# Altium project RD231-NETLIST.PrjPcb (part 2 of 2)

## Sheet 3.SchDoc
size 420 x 297 mm
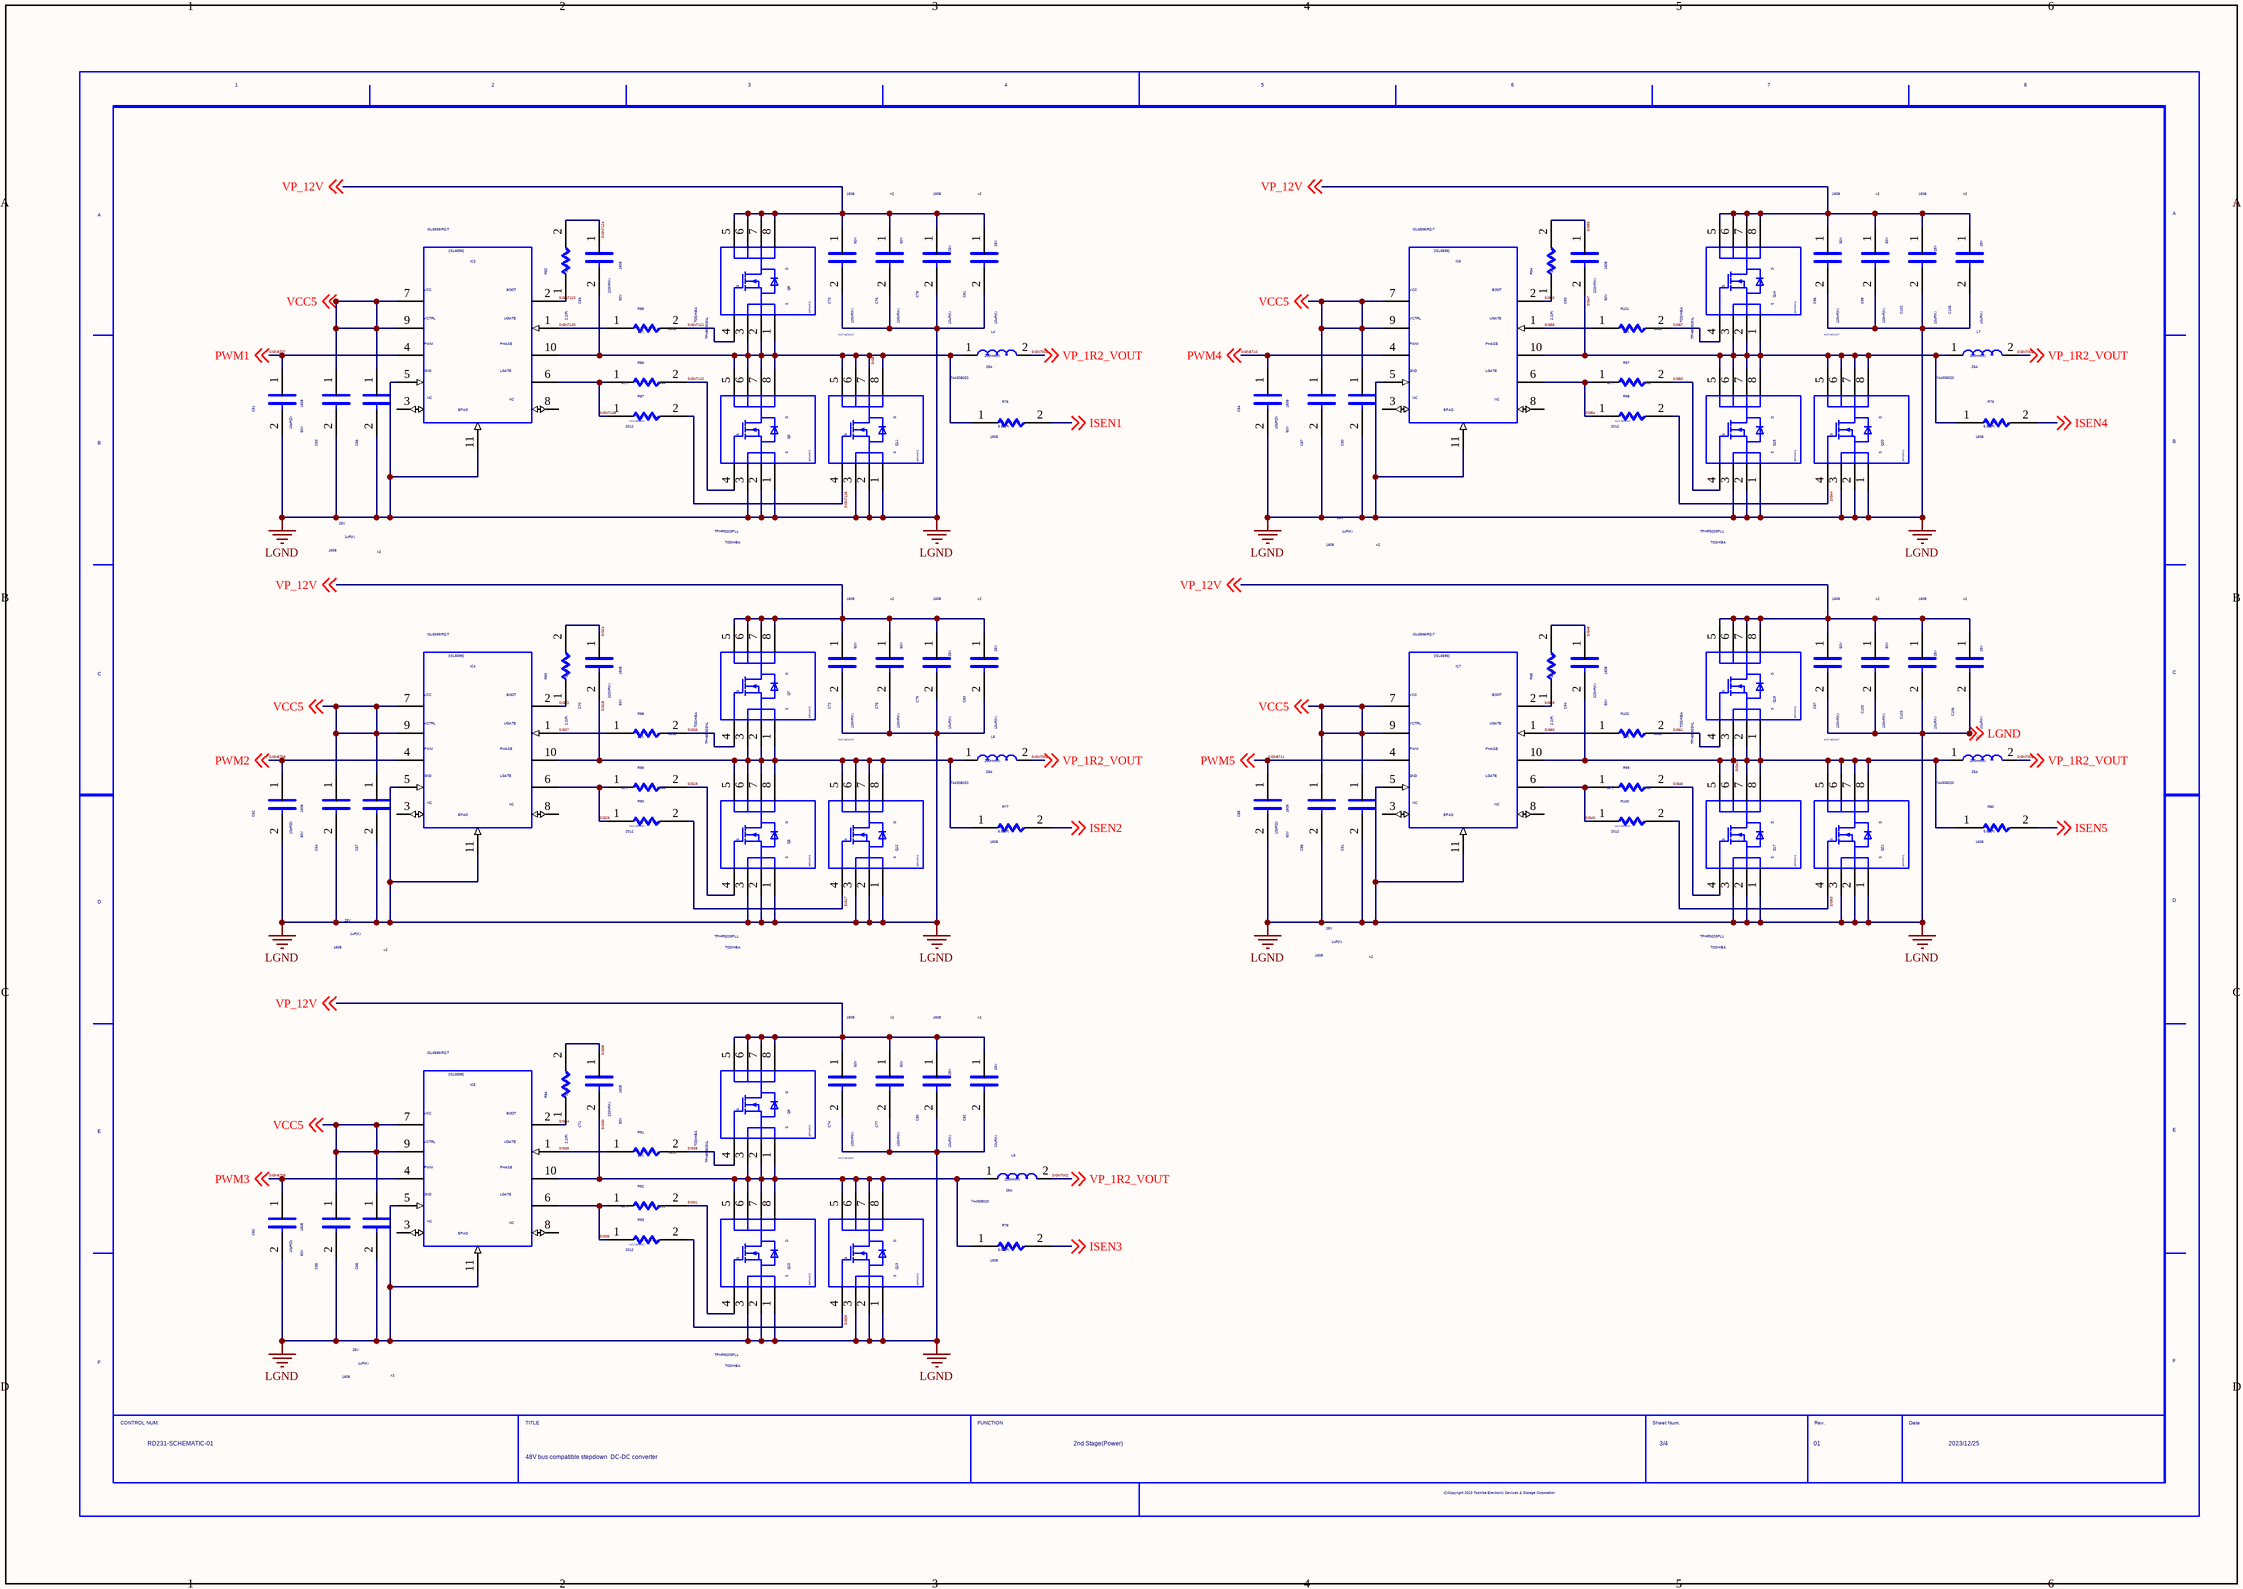
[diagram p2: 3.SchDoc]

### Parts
(Parts that share a designator on the sheet are numbered #1, #2 ... from top to bottom, then left to right.)
C60  VAL1: 10pF(D)  VAL2: 50V  SIZECODESMD: 1608  (hidden comment: C)
C61  VAL1: 10pF(D)  VAL2: 50V  SIZECODESMD: 1608  (hidden comment: C)
C62  VAL1: 10pF(D)  VAL2: 50V  SIZECODESMD: 1608  (hidden comment: C)
C63  C  (value not drawn)
C64  C  (value not drawn)
C65  C  (value not drawn)
C66  VAL1: 1uF(K)  VAL2: 25V  SIZECODESMD: 1608  (hidden comment: C)
C67  VAL1: 1uF(K)  VAL2: 25V  SIZECODESMD: 1608  (hidden comment: C)
C68  VAL1: 1uF(K)  VAL2: 25V  SIZECODESMD: 1608  (hidden comment: C)
C69  VAL1: 220nF(K)  VAL2: 50V  SIZECODESMD: 1608  (hidden comment: C)
C70  VAL1: 220nF(K)  VAL2: 50V  SIZECODESMD: 1608  (hidden comment: C)
C71  VAL1: 220nF(K)  VAL2: 50V  SIZECODESMD: 1608  (hidden comment: C)
C72  VAL1: 100nF(K)  VAL2: 50V  SIZECODESMD: 1608  (hidden comment: C)
C73  VAL1: 100nF(K)  VAL2: 50V  SIZECODESMD: 1608  (hidden comment: C)
C74  VAL1: 100nF(K)  VAL2: 50V  SIZECODESMD: 1608  (hidden comment: C)
C75  VAL1: 100nF(K)  VAL2: 50V  (hidden comment: C)
C76  VAL1: 100nF(K)  VAL2: 50V  (hidden comment: C)
C77  VAL1: 100nF(K)  VAL2: 50V  (hidden comment: C)
C78  VAL1: 10uF(K)  VAL2: 25V  SIZECODESMD: 1608  (hidden comment: C)
C79  VAL1: 10uF(K)  VAL2: 25V  SIZECODESMD: 1608  (hidden comment: C)
C80  VAL1: 10uF(K)  VAL2: 25V  SIZECODESMD: 1608  (hidden comment: C)
C81  VAL1: 10uF(K)  VAL2: 25V  (hidden comment: C)
C82  VAL1: 10uF(K)  VAL2: 25V  (hidden comment: C)
C83  VAL1: 10uF(K)  VAL2: 25V  (hidden comment: C)
C84  VAL1: 10pF(D)  VAL2: 50V  SIZECODESMD: 1608  (hidden comment: C)
C85  VAL1: 10pF(D)  VAL2: 50V  SIZECODESMD: 1608  (hidden comment: C)
C87  C  (value not drawn)
C88  C  (value not drawn)
C90  VAL1: 1uF(K)  VAL2: 25V  SIZECODESMD: 1608  (hidden comment: C)
C91  VAL1: 1uF(K)  VAL2: 25V  SIZECODESMD: 1608  (hidden comment: C)
C93  VAL1: 220nF(K)  VAL2: 50V  SIZECODESMD: 1608  (hidden comment: C)
C94  VAL1: 220nF(K)  VAL2: 50V  SIZECODESMD: 1608  (hidden comment: C)
C96  VAL1: 100nF(K)  VAL2: 50V  SIZECODESMD: 1608  (hidden comment: C)
C97  VAL1: 100nF(K)  VAL2: 50V  SIZECODESMD: 1608  (hidden comment: C)
C99  VAL1: 100nF(K)  VAL2: 50V  (hidden comment: C)
C100  VAL1: 100nF(K)  VAL2: 50V  (hidden comment: C)
C102  VAL1: 10uF(K)  VAL2: 25V  SIZECODESMD: 1608  (hidden comment: C)
C103  VAL1: 10uF(K)  VAL2: 25V  SIZECODESMD: 1608  (hidden comment: C)
C105  VAL1: 10uF(K)  VAL2: 25V  (hidden comment: C)
C106  VAL1: 10uF(K)  VAL2: 25V  (hidden comment: C)
IC3  VAL3: ISL6596IRZ-T  (hidden comment: ISL6596)
IC4  VAL3: ISL6596IRZ-T  (hidden comment: ISL6596)
IC5  VAL3: ISL6596IRZ-T  (hidden comment: ISL6596)
IC6  VAL3: ISL6596IRZ-T  (hidden comment: ISL6596)
IC7  VAL3: ISL6596IRZ-T  (hidden comment: ISL6596)
L4  VAL1: 200nH(M)  VAL2: 25A  VAL3: 744308020  (hidden comment: L)
L5  VAL1: 200nH(M)  VAL2: 25A  VAL3: 744308020  (hidden comment: L)
L6  VAL1: 200nH(M)  VAL2: 25A  VAL3: 744308020  (hidden comment: L)
L7  VAL1: 200nH(M)  VAL2: 25A  VAL3: 744308020  (hidden comment: L)
L8  VAL1: 200nH(M)  VAL2: 25A  VAL3: 744308020  (hidden comment: L)
Q5  VAL3: TPH8R903NL  USERCOMPTEXT3: TOSHIBA  (hidden comment: MFNKR2)
Q6  VAL3: TPHR9203PL1  USERCOMPTEXT3: TOSHIBA  (hidden comment: MFNKR2)
Q7  VAL3: TPH8R903NL  USERCOMPTEXT3: TOSHIBA  (hidden comment: MFNKR2)
Q8  VAL3: TPHR9203PL1  USERCOMPTEXT3: TOSHIBA  (hidden comment: MFNKR2)
Q9  VAL3: TPH8R903NL  USERCOMPTEXT3: TOSHIBA  (hidden comment: MFNKR2)
Q10  VAL3: TPHR9203PL1  USERCOMPTEXT3: TOSHIBA  (hidden comment: MFNKR2)
Q11  NOTMOUNT: NOT MOUNT  (hidden comment: MFNKR2)
Q12  NOTMOUNT: NOT MOUNT  (hidden comment: MFNKR2)
Q13  NOTMOUNT: NOT MOUNT  (hidden comment: MFNKR2)
Q14  VAL3: TPH8R903NL  USERCOMPTEXT3: TOSHIBA  (hidden comment: MFNKR2)
Q15  VAL3: TPHR9203PL1  USERCOMPTEXT3: TOSHIBA  (hidden comment: MFNKR2)
Q16  VAL3: TPH8R903NL  USERCOMPTEXT3: TOSHIBA  (hidden comment: MFNKR2)
Q17  VAL3: TPHR9203PL1  USERCOMPTEXT3: TOSHIBA  (hidden comment: MFNKR2)
Q20  NOTMOUNT: NOT MOUNT  (hidden comment: MFNKR2)
Q21  NOTMOUNT: NOT MOUNT  (hidden comment: MFNKR2)
R76  VAL1: 5.6k(F)  SIZECODESMD: 1608  (hidden comment: R)
R77  VAL1: 5.6k(F)  SIZECODESMD: 1608  (hidden comment: R)
R78  VAL1: 5.6k(F)  SIZECODESMD: 1608  (hidden comment: R)
R79  VAL1: 5.6k(F)  SIZECODESMD: 1608  (hidden comment: R)
R80  VAL1: 5.6k(F)  SIZECODESMD: 1608  (hidden comment: R)
R82  VAL1: 2.2(F)  SIZECODESMD: 2012  (hidden comment: R)
R83  VAL1: 2.2(F)  SIZECODESMD: 2012  (hidden comment: R)
R84  VAL1: 2.2(F)  SIZECODESMD: 2012  (hidden comment: R)
R85  VAL1: 1(F)  SIZECODESMD: 2012  (hidden comment: R)
R86  VAL1: 1(F)  SIZECODESMD: 2012  (hidden comment: R)
R87  NOTMOUNT: NOT MOUNT  SIZECODESMD: 2012  (hidden comment: R)
R88  VAL1: 1(F)  SIZECODESMD: 2012  (hidden comment: R)
R89  VAL1: 1(F)  SIZECODESMD: 2012  (hidden comment: R)
R90  NOTMOUNT: NOT MOUNT  SIZECODESMD: 2012  (hidden comment: R)
R91  VAL1: 1(F)  SIZECODESMD: 2012  (hidden comment: R)
R92  VAL1: 1(F)  SIZECODESMD: 2012  (hidden comment: R)
R93  NOTMOUNT: NOT MOUNT  SIZECODESMD: 2012  (hidden comment: R)
R94  VAL1: 2.2(F)  SIZECODESMD: 2012  (hidden comment: R)
R95  VAL1: 2.2(F)  SIZECODESMD: 2012  (hidden comment: R)
R97  VAL1: 1(F)  SIZECODESMD: 2012  (hidden comment: R)
R98  NOTMOUNT: NOT MOUNT  SIZECODESMD: 2012  (hidden comment: R)
R99  VAL1: 1(F)  SIZECODESMD: 2012  (hidden comment: R)
R100  NOTMOUNT: NOT MOUNT  SIZECODESMD: 2012  (hidden comment: R)
R101  VAL1: 1(F)  SIZECODESMD: 2012  (hidden comment: R)
R102  VAL1: 1(F)  SIZECODESMD: 2012  (hidden comment: R)
U?#3  DATE: 2023/12/25  FUNCTION: 2nd Stage(Power)  DRAWINGNUMBER: RD231-SCHEMATIC-01  SHEETNUMBER: 3/4  REVISION: 01  TITLE: 48V bus compatible stepdown / DC-DC converter  (hidden comment: WAKU_DEF100)

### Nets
LGND: C60.2 C61.2 C62.2 C63.2 C64.2 C65.2 C66.2 C67.2 C68.2 C72.2 C73.2 C74.2 C75.2 C76.2 C77.2 C78.2 C79.2 C80.2 C81.2 C82.2 C83.2 C84.2 C85.2 C87.2 C88.2 C90.2 C91.2 C96.2 C97.2 C99.2 C100.2 C102.2 C103.2 C105.2 C106.2 IC3.5 IC3.11 IC4.5 IC4.11 IC5.5 IC5.11 IC6.5 IC6.11 IC7.5 IC7.11 Q6.1 Q6.2 Q6.3 Q8.1 Q8.2 Q8.3 Q10.1 Q10.2 Q10.3 Q11.1 Q11.2 Q11.3 Q12.1 Q12.2 Q12.3 Q13.1 Q13.2 Q13.3 Q15.1 Q15.2 Q15.3 Q17.1 Q17.2 Q17.3 Q20.1 Q20.2 Q20.3 Q21.1 Q21.2 Q21.3 ; off-sheet LGND
ISEN1: R76.2 ; off-sheet ISEN1
ISEN2: R77.2 ; off-sheet ISEN2
ISEN3: R78.2 ; off-sheet ISEN3
ISEN4: R79.2 ; off-sheet ISEN4
ISEN5: R80.2 ; off-sheet ISEN5
SIG5: C69.2 IC3.10 L4.1 Q5.1 Q5.2 Q5.3 Q6.5 Q6.6 Q6.7 Q6.8 Q11.5 Q11.6 Q11.7 Q11.8 R76.1
SIG17: Q12.4 R90.2
SIG18: C70.2 IC4.10 L5.1 Q7.1 Q7.2 Q7.3 Q8.5 Q8.6 Q8.7 Q8.8 Q12.5 Q12.6 Q12.7 Q12.8 R77.1
SIG19: Q8.4 R89.2
SIG22: IC4.2 R83.1
SIG23: IC4.6 R89.1 R90.1
SIG24: C70.1 R83.2
SIG26: Q7.4 R88.2
SIG27: IC4.1 R88.1
SIG29: Q13.4 R93.2
SIG30: C71.2 IC5.10 L6.1 Q9.1 Q9.2 Q9.3 Q10.5 Q10.6 Q10.7 Q10.8 Q13.5 Q13.6 Q13.7 Q13.8 R78.1
SIG31: Q10.4 R92.2
SIG34: IC5.2 R84.1
SIG35: IC5.6 R92.1 R93.1
SIG36: C71.1 R84.2
SIG38: Q9.4 R91.2
SIG39: IC5.1 R91.1
SIG41: C94.2 IC7.10 L8.1 Q16.1 Q16.2 Q16.3 Q17.5 Q17.6 Q17.7 Q17.8 Q21.5 Q21.6 Q21.7 Q21.8 R80.1
SIG43: IC7.6 R99.1 R100.1
SIG44: Q20.4 R98.2
SIG46: Q17.4 R99.2
SIG47: C93.2 IC6.10 L7.1 Q14.1 Q14.2 Q14.3 Q15.5 Q15.6 Q15.7 Q15.8 Q20.5 Q20.6 Q20.7 Q20.8 R79.1
SIG48: C94.1 R95.2
SIG49: IC7.2 R95.1
SIG50: Q15.4 R97.2
SIG53: IC6.2 R94.1
SIG54: IC6.6 R97.1 R98.1
SIG55: C93.1 R94.2
SIG57: Q14.4 R101.2
SIG58: IC6.1 R101.1
SIG60: IC7.1 R102.1
SIG61: Q16.4 R102.2
SIG63: Q21.4 R100.2
SIGN6707: C61.1 IC3.4 ; off-sheet PWM1  [also labelled PWM1]
SIGN6708: C62.1 IC4.4 ; off-sheet PWM2  [also labelled PWM2]
SIGN6709: C60.1 IC5.4 ; off-sheet PWM3  [also labelled PWM3]
SIGN6710: C84.1 IC6.4 ; off-sheet PWM4  [also labelled PWM4]
SIGN6711: C85.1 IC7.4 ; off-sheet PWM5  [also labelled PWM5]
SIGN7002: L4.2 L5.2 L6.2 L7.2 L8.2 ; off-sheet VP_1R2_VOUT  [also labelled VP_1R2_VOUT]
SIGN7120: IC3.1 R85.1
SIGN7121: Q5.4 R85.2
SIGN7122: Q6.4 R86.2
SIGN7123: IC3.2 R82.1
SIGN7124: C69.1 R82.2
SIGN7125: Q11.4 R87.2
SIGN7126: IC3.6 R86.1 R87.1
VCC5: C63.1 C64.1 C65.1 C66.1 C67.1 C68.1 C87.1 C88.1 C90.1 C91.1 IC3.7 IC3.9 IC4.7 IC4.9 IC5.7 IC5.9 IC6.7 IC6.9 IC7.7 IC7.9 ; off-sheet VCC5
VP_12V: C72.1 C73.1 C74.1 C75.1 C76.1 C77.1 C78.1 C79.1 C80.1 C81.1 C82.1 C83.1 C96.1 C97.1 C99.1 C100.1 C102.1 C103.1 C105.1 C106.1 Q5.5 Q5.6 Q5.7 Q5.8 Q7.5 Q7.6 Q7.7 Q7.8 Q9.5 Q9.6 Q9.7 Q9.8 Q14.5 Q14.6 Q14.7 Q14.8 Q16.5 Q16.6 Q16.7 Q16.8 ; off-sheet VP_12V

Not connected (* = marked no-connect by the designer): IC3 3 8; IC4 3 8; IC5 3 8; IC6 3 8; IC7 3 8

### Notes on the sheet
- x2

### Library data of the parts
C60-C62 C84 C85 = C: FNPARTSNAMEG: CHIP CERAMIC CAPACITOR (1608); OriginalSymbolOrigin: (2540,7620); FNCLASSCODEG: P03-03; PCODE: P03039185229; USEWITHSCHEMA: YES; MFMOUNTSYMBOLP: 80; FUNCN: G36030011013; MFFORMINGDIVP: KC; MFPACKAGEMETHOP: S; MFSOLDERINGPROP: .; COMPONENTNAME: G36030011013_package; GCOUNT: 1; TOLERANCE: D
C63-C65 C87 C88 = C: FNPARTSNAMEG: CHIP CERAMIC CAPACITOR (1608); OriginalSymbolOrigin: (2540,7620); FNCLASSCODEG: P03-03; PCODE: P03039992230; USEWITHSCHEMA: YES; VAL1: 1uF(K); VAL2: 25V; MFMOUNTSYMBOLP: 80; FUNCN: G36030011433; SIZECODESMD: 1608; MFFORMINGDIVP: KC; MFPACKAGEMETHOP: S; MFSOLDERINGPROP: .; COMPONENTNAME: G36030011433_package; GCOUNT: 1
C66-C68 C78-C80 C90 C91 C102 C103 = C: FNPARTSNAMEG: CHIP CERAMIC CAPACITOR (1608); OriginalSymbolOrigin: (2540,7620); FNCLASSCODEG: P03-03; PCODE: P03039992230; USEWITHSCHEMA: YES; MFMOUNTSYMBOLP: 80; FUNCN: G36030011433; MFFORMINGDIVP: KC; MFPACKAGEMETHOP: S; MFSOLDERINGPROP: .; COMPONENTNAME: G36030011433_package; GCOUNT: 1
C69-C71 C93 C94 = C: FNPARTSNAMEG: CHIP CERAMIC CAPACITOR (1608); OriginalSymbolOrigin: (2540,7620); FNCLASSCODEG: P03-03; PCODE: P03039ABE123; USEWITHSCHEMA: YES; MFMOUNTSYMBOLP: 80; FUNCN: G36030104104; MFFORMINGDIVP: KC; MFPACKAGEMETHOP: S; MFSOLDERINGPROP: .; COMPONENTNAME: G36030104104_package; GCOUNT: 1
C72-C74 C96 C97 = C: FNPARTSNAMEG: CHIP CERAMIC CAPACITOR (1608); OriginalSymbolOrigin: (2540,7620); FNCLASSCODEG: P03-03; PCODE: P03039996139; USEWITHSCHEMA: YES; MFMOUNTSYMBOLP: 80; FUNCN: G36030011419; MFFORMINGDIVP: KC; MFPACKAGEMETHOP: S; MFSOLDERINGPROP: .; COMPONENTNAME: G36030011419_package; GCOUNT: 1
C75-C77 C99 C100 = C: FNPARTSNAMEG: CHIP CERAMIC CAPACITOR (1608); OriginalSymbolOrigin: (2540,7620); FNCLASSCODEG: P03-03; PCODE: P03039996139; USEWITHSCHEMA: YES; MFMOUNTSYMBOLP: 80; FUNCN: G36030011419; SIZECODESMD: 1608; MFFORMINGDIVP: KC; MFPACKAGEMETHOP: S; MFSOLDERINGPROP: .; COMPONENTNAME: G36030011419_package; GCOUNT: 1
C81-C83 C105 C106 = C: FNPARTSNAMEG: CHIP CERAMIC CAPACITOR (1608); OriginalSymbolOrigin: (2540,7620); FNCLASSCODEG: P03-03; PCODE: P03039992230; USEWITHSCHEMA: YES; MFMOUNTSYMBOLP: 80; FUNCN: G36030011433; SIZECODESMD: 1608; MFFORMINGDIVP: KC; MFPACKAGEMETHOP: S; MFSOLDERINGPROP: .; COMPONENTNAME: G36030011433_package; GCOUNT: 1
IC3-IC7 = ISL6596: PARTS: 1; SAVECOUNT: 32; SAVEAREA0: -56845,-25936,87219,39707; TIME: 14:04:55; UPDATEUSER: sptcae13; UPDATETIME: 17:09:04; DEVICENAME: 74HC244AF; DEVICE: 74VHC245; PKG_TYPE: 20PIN; LEVEL: STD; HETERO: 74VHC245,74VHC245_P; OriginalSymbolOrigin: (5080,27940); COMP: G36470287016
L4-L8 = L: OriginalSymbolOrigin: (2540,5080); USEWITHSCHEMA: YES; OUMEMAKERKATAMEI: 7443082022; OUMEMAKER: Wurth; COMPONENTNAME: pinass:L_func:L; GCOUNT: 1
Q5-Q10 Q14-Q17 = MFNKR2: SAVEAREA0: -9199,-39,32138,22820; TIME: 18:57:44; UPDATEUSER: q91866sr; UPDATETIME: 12:36:02; SAVECOUNT: 10; OriginalSymbolOrigin: (5080,20320); USEWITHSCHEMA: YES; OUMEMAKERKATAMEI: TPH6R003NL; COMPONENTNAME: MFNKR2_MFNKR2; GCOUNT: 1
Q11-Q13 Q20 Q21 = MFNKR2: SAVEAREA0: -9199,-39,32138,22820; TIME: 18:57:44; UPDATEUSER: q91866sr; UPDATETIME: 12:36:02; SAVECOUNT: 10; OriginalSymbolOrigin: (5080,20320); USEWITHSCHEMA: YES; OUMEMAKERKATAMEI: TPH6R003NL; OUMEMAKER: TOSHIBA; COMPONENTNAME: MFNKR2_MFNKR2; GCOUNT: 1
R76-R80 = R: OriginalSymbolOrigin: (5080,5080); VAL2: 62.5mW
R82-R84 R94 R95 = R: FNPARTSNAMEG: CHIP RESISTOR (2012); OriginalSymbolOrigin: (5080,5080); FNCLASSCODEG: P01-08; PCODE: P01048019214; USEWITHSCHEMA: YES; VAL2: 125mW; NUMBEROFELEMENT: 0; MFMOUNTSYMBOLP: 90; FUNCN: G36010106012; MFFORMINGDIVP: KC; MFPACKAGEMETHOP: S; MFSOLDERINGPROP: .; COMPONENTNAME: G36010106012_package; GCOUNT: 1
R85 R86 R88 R89 R91 R92 R97 R99 R101 R102 = R: FNPARTSNAMEG: CHIP RESISTOR (2012); OriginalSymbolOrigin: (5080,5080); FNCLASSCODEG: P01-08; PCODE: P01048017210; USEWITHSCHEMA: YES; VAL2: 125mW; NUMBEROFELEMENT: 0; MFMOUNTSYMBOLP: 90; FUNCN: G36010106081; MFFORMINGDIVP: KC; MFPACKAGEMETHOP: S; MFSOLDERINGPROP: .; COMPONENTNAME: G36010106081_package; GCOUNT: 1
R87 R90 R93 R98 R100 = R: FNPARTSNAMEG: CHIP RESISTOR (2012); OriginalSymbolOrigin: (5080,5080); FNCLASSCODEG: P01-08; PCODE: P01048017210; USEWITHSCHEMA: YES; NUMBEROFELEMENT: 0; MFMOUNTSYMBOLP: 90; FUNCN: G36010106081; MFFORMINGDIVP: KC; MFPACKAGEMETHOP: S; MFSOLDERINGPROP: .; COMPONENTNAME: G36010106081_package; GCOUNT: 1
U?#3 = WAKU_DEF100: PLOTTIME: HH:MM; SAVEAREA0: 315434,-7824,400773,39368; TIME: 14:26:19; UPDATEUSER: sptcae13; UPDATETIME: 11:36:35; SAVECOUNT: 8; OriginalSymbolOrigin: (10160,284480)

## Sheet 4.SchDoc
size 420 x 297 mm
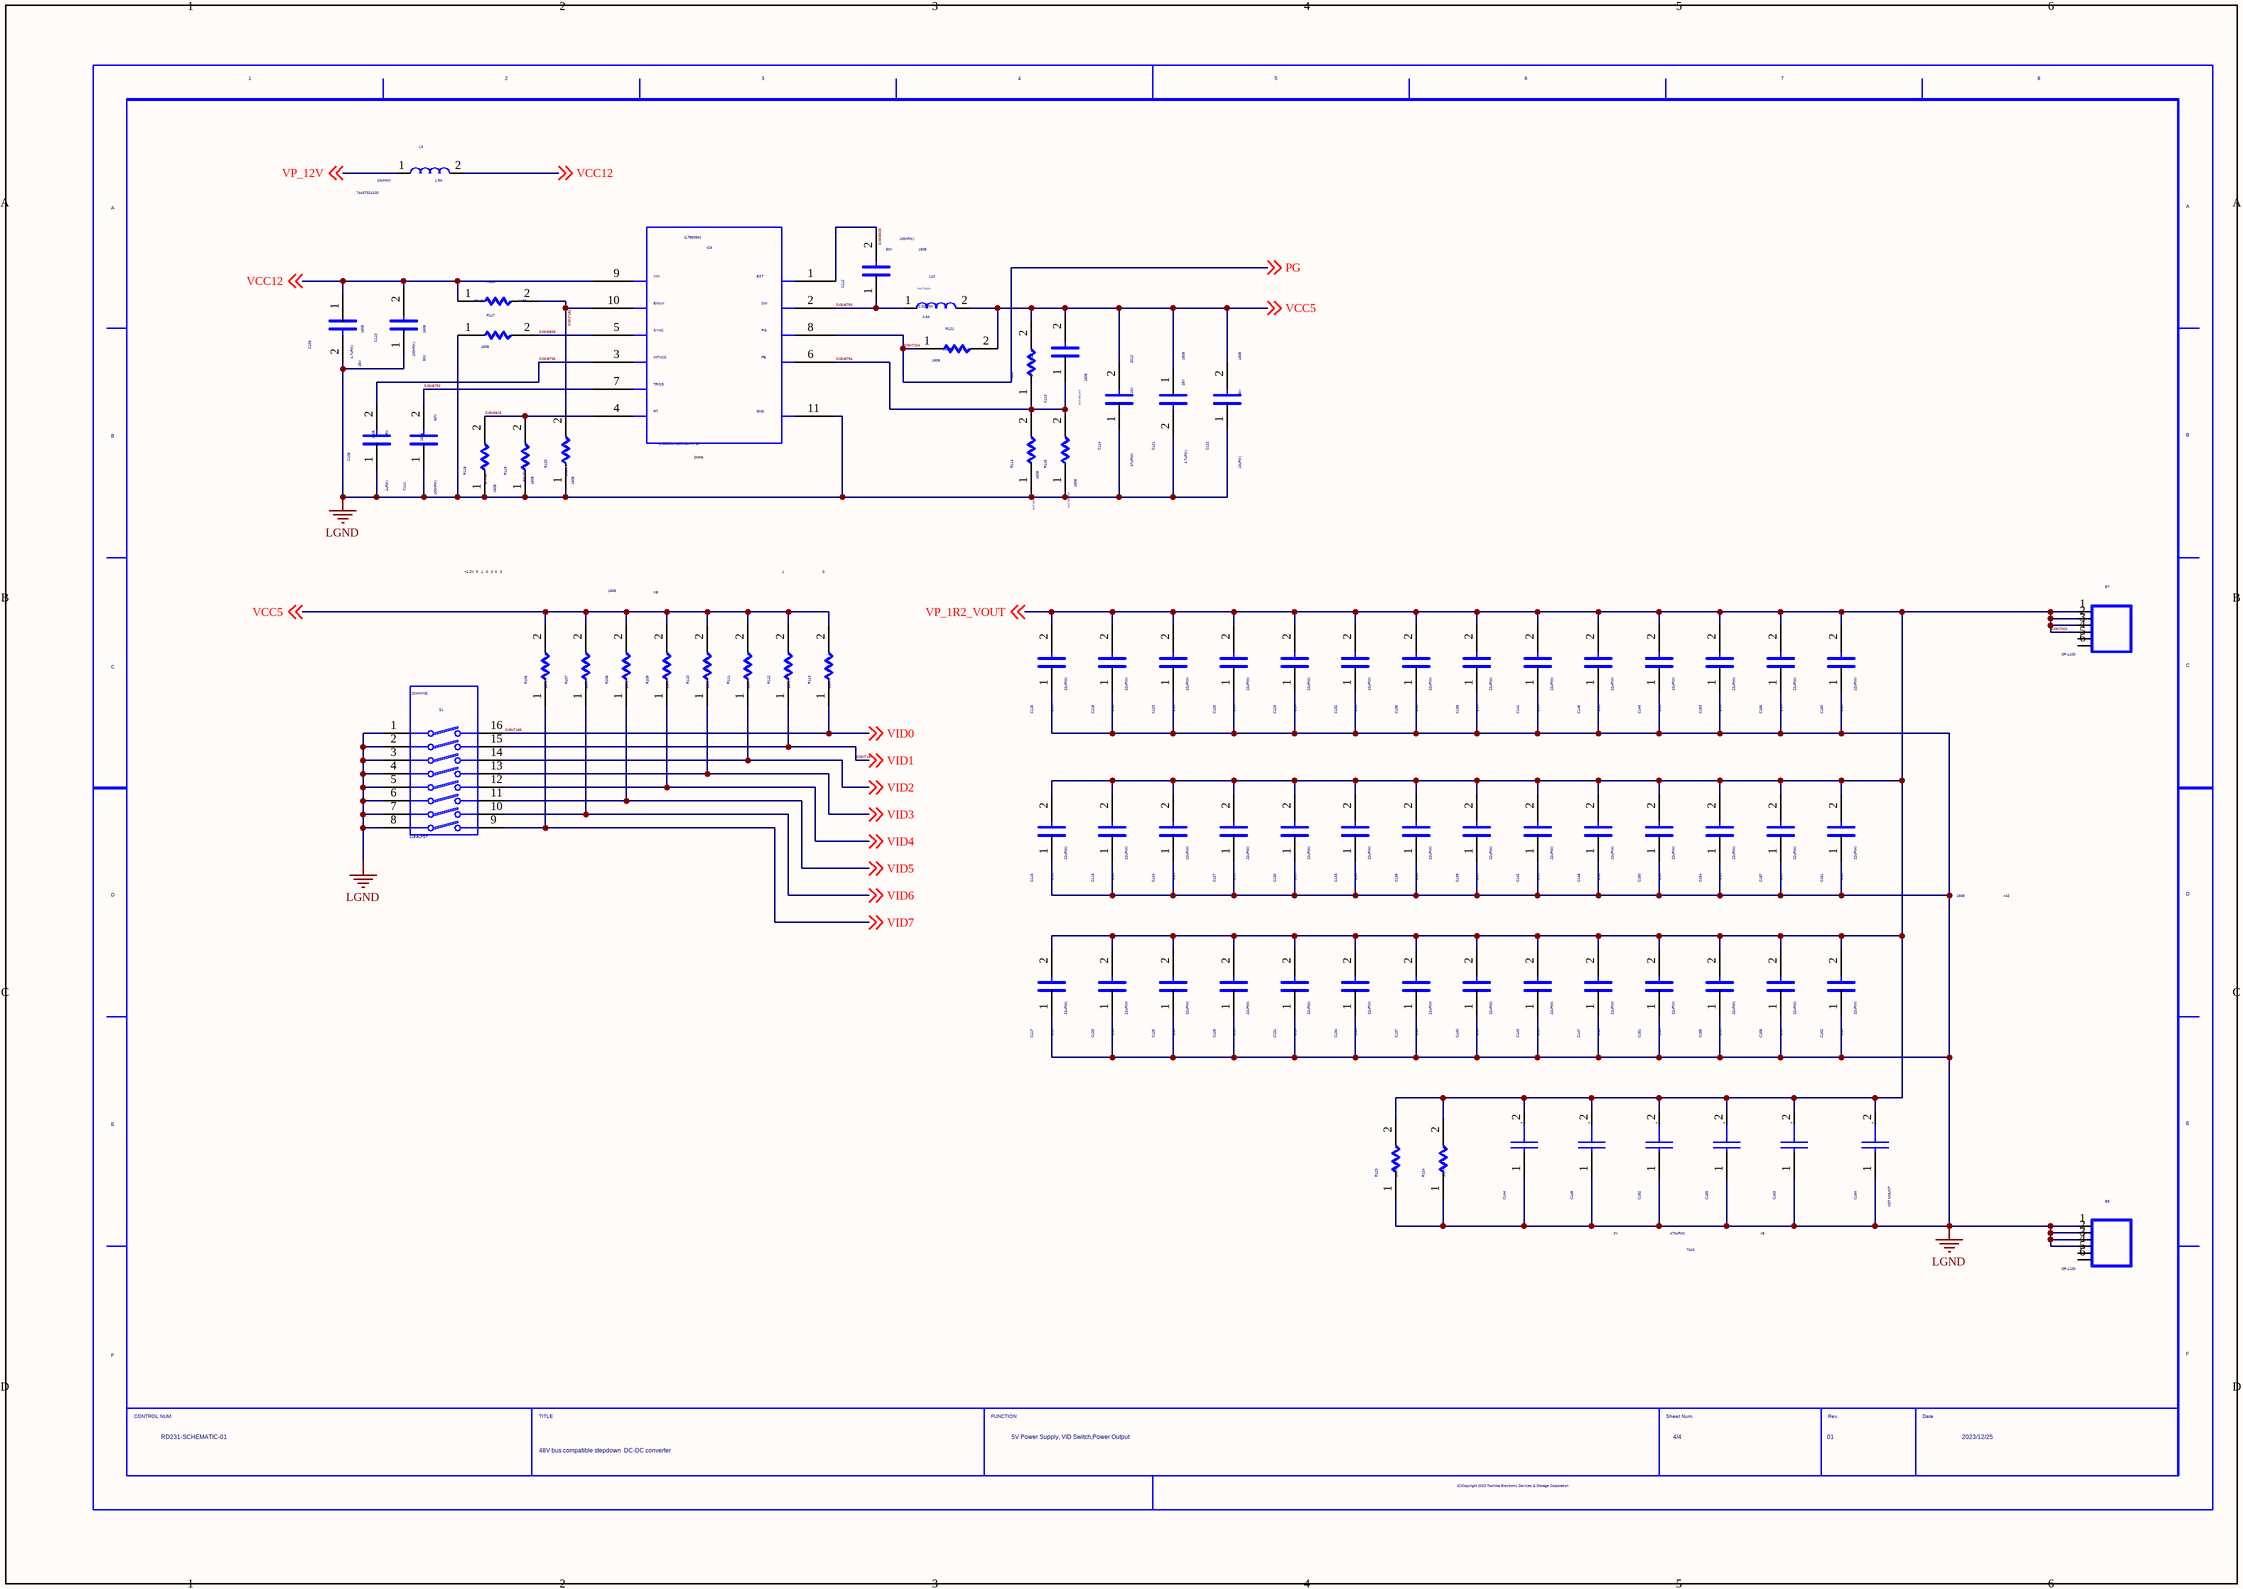
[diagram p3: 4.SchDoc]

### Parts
(Parts that share a designator on the sheet are numbered #1, #2 ... from top to bottom, then left to right.)
C108  VAL1: 1uF(K)  VAL2: 25V  SIZECODESMD: 1608  (hidden comment: C)
C109  VAL1: 4.7uF(K)  VAL2: 25V  SIZECODESMD: 1608  (hidden comment: C)
C110  VAL1: 100nF(K)  VAL2: 50V  SIZECODESMD: 1608  (hidden comment: C)
C111  VAL1: 100nF(K)  VAL2: 50V  SIZECODESMD: 1608  (hidden comment: C)
C112  VAL1: 100nF(K)  VAL2: 50V  SIZECODESMD: 1608  (hidden comment: C)
C113  NOTMOUNT: NOT MOUNT  SIZECODESMD: 1608  (hidden comment: C)
C114  VAL1: 47uF(M)  VAL2: 10V  SIZECODESMD: 2012  (hidden comment: C)
C115  VAL1: 22uF(M)  VAL2: 6.3V  (hidden comment: C)
C116  VAL1: 22uF(M)  VAL2: 6.3V  (hidden comment: C)
C117  VAL1: 22uF(M)  VAL2: 6.3V  (hidden comment: C)
C118  VAL1: 22uF(M)  VAL2: 6.3V  (hidden comment: C)
C119  VAL1: 22uF(M)  VAL2: 6.3V  (hidden comment: C)
C120  VAL1: 22uF(M)  VAL2: 6.3V  (hidden comment: C)
C121  VAL1: 4.7uF(K)  VAL2: 25V  SIZECODESMD: 1608  (hidden comment: C)
C122  VAL1: 10uF(K)  VAL2: 25V  SIZECODESMD: 1608  (hidden comment: C)
C123  VAL1: 22uF(M)  VAL2: 6.3V  (hidden comment: C)
C124  VAL1: 22uF(M)  VAL2: 6.3V  (hidden comment: C)
C125  VAL1: 22uF(M)  VAL2: 6.3V  (hidden comment: C)
C126  VAL1: 22uF(M)  VAL2: 6.3V  (hidden comment: C)
C127  VAL1: 22uF(M)  VAL2: 6.3V  (hidden comment: C)
C128  VAL1: 22uF(M)  VAL2: 6.3V  (hidden comment: C)
C129  VAL1: 22uF(M)  VAL2: 6.3V  (hidden comment: C)
C130  VAL1: 22uF(M)  VAL2: 6.3V  (hidden comment: C)
C131  VAL1: 22uF(M)  VAL2: 6.3V  (hidden comment: C)
C132  VAL1: 22uF(M)  VAL2: 6.3V  (hidden comment: C)
C133  VAL1: 22uF(M)  VAL2: 6.3V  (hidden comment: C)
C134  VAL1: 22uF(M)  VAL2: 6.3V  (hidden comment: C)
C135  VAL1: 22uF(M)  VAL2: 6.3V  (hidden comment: C)
C136  VAL1: 22uF(M)  VAL2: 6.3V  (hidden comment: C)
C137  VAL1: 22uF(M)  VAL2: 6.3V  (hidden comment: C)
C138  VAL1: 22uF(M)  VAL2: 6.3V  (hidden comment: C)
C139  VAL1: 22uF(M)  VAL2: 6.3V  (hidden comment: C)
C140  VAL1: 22uF(M)  VAL2: 6.3V  (hidden comment: C)
C141  VAL1: 22uF(M)  VAL2: 6.3V  (hidden comment: C)
C142  VAL1: 22uF(M)  VAL2: 6.3V  (hidden comment: C)
C143  VAL1: 22uF(M)  VAL2: 6.3V  (hidden comment: C)
C144  VAL1: 470uF(M)  VAL2: 2V  SIZECODESMD: 7343  (hidden comment: CP)
C145  VAL1: 22uF(M)  VAL2: 6.3V  (hidden comment: C)
C146  VAL1: 22uF(M)  VAL2: 6.3V  (hidden comment: C)
C147  VAL1: 22uF(M)  VAL2: 6.3V  (hidden comment: C)
C148  CP  (value not drawn)
C149  VAL1: 22uF(M)  VAL2: 6.3V  (hidden comment: C)
C150  VAL1: 22uF(M)  VAL2: 6.3V  (hidden comment: C)
C151  VAL1: 22uF(M)  VAL2: 6.3V  (hidden comment: C)
C152  CP  (value not drawn)
C153  VAL1: 22uF(M)  VAL2: 6.3V  (hidden comment: C)
C154  VAL1: 22uF(M)  VAL2: 6.3V  (hidden comment: C)
C155  VAL1: 22uF(M)  VAL2: 6.3V  (hidden comment: C)
C156  VAL1: 22uF(M)  VAL2: 6.3V  (hidden comment: C)
C157  VAL1: 22uF(M)  VAL2: 6.3V  (hidden comment: C)
C158  VAL1: 22uF(M)  VAL2: 6.3V  (hidden comment: C)
C159  CP  (value not drawn)
C160  VAL1: 22uF(M)  VAL2: 6.3V  (hidden comment: C)
C161  VAL1: 22uF(M)  VAL2: 6.3V  SIZECODESMD: 1608  (hidden comment: C)
C162  VAL1: 22uF(M)  VAL2: 6.3V  (hidden comment: C)
C163  CP  (value not drawn)
C164  NOTMOUNT: NOT MOUNT  (hidden comment: CP)
E7  VAL3: OP-1100  (hidden comment: EB1)
E8  VAL3: OP-1100  (hidden comment: EB1)
IC9  COMP: LT8609AHDDM-5#TRPBF  (hidden comment: LT8609A)
L3  VAL1: 10uH(M)  VAL2: 1.5A  VAL3: 74437324100  (hidden comment: L)
L10  COMP: 744774022  VAL1: 2.2uH(M)  VAL2: 4.6A  (hidden comment: L)
R106  VAL1: 10k(F)  SIZECODESMD: 1608  (hidden comment: R)
R107  VAL1: 10k(F)  (hidden comment: R)
R108  VAL1: 10k(F)  (hidden comment: R)
R109  VAL1: 10k(F)  (hidden comment: R)
R110  VAL1: 10k(F)  (hidden comment: R)
R111  VAL1: 10k(F)  (hidden comment: R)
R112  VAL1: 10k(F)  (hidden comment: R)
R113  VAL1: 10k(F)  (hidden comment: R)
R114  NOTMOUNT: NOT MOUNT  SIZECODESMD: 1608  (hidden comment: R)
R115  NOTMOUNT: NOT MOUNT  SIZECODESMD: 1608  (hidden comment: R)
R116  VAL1: 33k(F)  SIZECODESMD: 1608  (hidden comment: R)
R117  VAL1: 0  SIZECODESMD: 1608  (hidden comment: R)
R118  VAL1: 27k(D)  SIZECODESMD: 1608  (hidden comment: R)
R119  VAL1: 56k(D)  SIZECODESMD: 1608  (hidden comment: R)
R120  VAL1: 3.9k(F)  SIZECODESMD: 1608  (hidden comment: R)
R121  VAL1: 10k(F)  SIZECODESMD: 1608  (hidden comment: R)
R122  VAL1: 0  SIZECODESMD: 1608  (hidden comment: R)
R123  VAL1: 1k(F)  (hidden comment: R)
R124  VAL1: 1k(F)  (hidden comment: R)
S1  COMP: 219-8LPST  (hidden comment: SWMX8)
U?#4  DATE: 2023/12/25  FUNCTION: 5V Power Supply, VID Switch,Power Output  DRAWINGNUMBER: RD231-SCHEMATIC-01  SHEETNUMBER: 4/4  REVISION: 01  TITLE: 48V bus compatible stepdown / DC-DC converter  (hidden comment: WAKU_DEF100)

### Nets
LGND: C108.1 C109.2 C110.1 C111.1 C114.1 C115.1 C116.1 C117.1 C118.1 C119.1 C120.1 C121.2 C122.1 C123.1 C124.1 C125.1 C126.1 C127.1 C128.1 C129.1 C130.1 C131.1 C132.1 C133.1 C134.1 C135.1 C136.1 C137.1 C138.1 C139.1 C140.1 C141.1 C142.1 C143.1 C144.1 C145.1 C146.1 C147.1 C148.1 C149.1 C150.1 C151.1 C152.1 C153.1 C154.1 C155.1 C156.1 C157.1 C158.1 C159.1 C160.1 C161.1 C162.1 C163.1 C164.1 E8.1 E8.2 E8.3 E8.4 IC9.11 R114.1 R115.1 R117.1 R118.1 R119.1 R120.1 R123.1 R124.1 S1.1 S1.2 S1.3 S1.4 S1.5 S1.6 S1.7 S1.8
SIGN6792: C111.2 IC9.7
SIGN6793: C112.1 IC9.2 L10.1
SIGN6794: C113.1 IC9.6 R114.2 R115.2 R122.1
SIGN6796: C108.2 IC9.3
SIGN6815: IC9.4 R118.2 R119.2
SIGN6828: C112.2 IC9.1
SIGN6838: IC9.5 R117.2
SIGN7002: C115.2 C116.2 C117.2 C118.2 C119.2 C120.2 C123.2 C124.2 C125.2 C126.2 C127.2 C128.2 C129.2 C130.2 C131.2 C132.2 C133.2 C134.2 C135.2 C136.2 C137.2 C138.2 C139.2 C140.2 C141.2 C142.2 C143.2 C144.2 C145.2 C146.2 C147.2 C148.2 C149.2 C150.2 C151.2 C152.2 C153.2 C154.2 C155.2 C156.2 C157.2 C158.2 C159.2 C160.2 C161.2 C162.2 C163.2 C164.2 E7.1 E7.2 E7.3 E7.4 R123.2 R124.2 ; off-sheet VP_1R2_VOUT  [also labelled VP_1R2_VOUT]
SIGN7182: IC9.10 R116.2 R120.2
SIGN7186: R113.1 S1.16 ; off-sheet VID0  [also labelled VID0]
SIGN7187: R112.1 S1.15 ; off-sheet VID1  [also labelled VID1]
SIGN7204: IC9.8 R121.1 ; off-sheet PG  [also labelled PG]
VCC5: C113.2 C114.2 C121.1 C122.2 L10.2 R106.2 R107.2 R108.2 R109.2 R110.2 R111.2 R112.2 R113.2 R121.2 R122.2 ; off-sheet VCC5
VCC12: C109.1 C110.2 IC9.9 L3.2 R116.1 ; off-sheet VCC12
VID2: R111.1 S1.14 ; off-sheet VID2
VID3: R110.1 S1.13 ; off-sheet VID3
VID4: R109.1 S1.12 ; off-sheet VID4
VID5: R108.1 S1.11 ; off-sheet VID5
VID6: R107.1 S1.10 ; off-sheet VID6
VID7: R106.1 S1.9 ; off-sheet VID7
VP_12V: L3.1 ; off-sheet VP_12V

Not connected (* = marked no-connect by the designer): E7 5 6; E8 5 6

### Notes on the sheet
- (near IC9) 2MHz
- +1.2V  0   1   0   0  0   0
- X8
- 1
- 0
- x42
- x5

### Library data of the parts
C108 = C: FNPARTSNAMEG: CHIP CERAMIC CAPACITOR (1608); OriginalSymbolOrigin: (2540,7620); USEWITHSCHEMA: YES; FUNCN: G36030011433; MFPACKAGEMETHOP: S; COMPONENTNAME: G36030011433_package; GCOUNT: 1; FNCLASSCODEG: P03-03; MFMOUNTSYMBOLP: 80; MFFORMINGDIVP: KC; MFSOLDERINGPROP: .; PCODE: P03039992230
C109 = C: FNPARTSNAMEG: CHIP CERAMIC CAPACITOR (1608); OriginalSymbolOrigin: (2540,7620); FNCLASSCODEG: P03-03; PCODE: P03B000000MS; USEWITHSCHEMA: YES; MFMOUNTSYMBOLP: 80; FUNCN: GDM030000053; MFFORMINGDIVP: KC; MFPACKAGEMETHOP: S; MFSOLDERINGPROP: .; COMPONENTNAME: GDM030000053_package; GCOUNT: 1
C110 C112 = C: FNPARTSNAMEG: CHIP CERAMIC CAPACITOR (1608); OriginalSymbolOrigin: (2540,7620); USEWITHSCHEMA: YES; FUNCN: G36030104036; MFPACKAGEMETHOP: S; COMPONENTNAME: G36030104036_package; GCOUNT: 1; FNCLASSCODEG: P03-03; PCODE: P03039A6F224; MFMOUNTSYMBOLP: 80; MFFORMINGDIVP: KC; MFSOLDERINGPROP: .
C111 = C: PARTCOMMENT: 代表セル<KC0008> がフットプリントに登録されていません。; FNPARTSNAMEG: CHIP CERAMIC CAPACITOR (1608); OriginalSymbolOrigin: (2540,7620); USEWITHSCHEMA: YES; FUNCN: GDM030001137; MFPACKAGEMETHOP: S; COMPONENTNAME: GDM030001137_package; GCOUNT: 1; FNCLASSCODEG: P03-03; PCODE: P03B000001KW; MFMOUNTSYMBOLP: 80; MFFORMINGDIVP: KC; MFSOLDERINGPROP: .
C113 = C: FNPARTSNAMEG: CHIP CERAMIC CAPACITOR (1608); OriginalSymbolOrigin: (2540,7620); USEWITHSCHEMA: YES; FUNCN: G36030011013; MFPACKAGEMETHOP: S; COMPONENTNAME: G36030011013_package; GCOUNT: 1; FNCLASSCODEG: P03-03; PCODE: P03039185229; MFMOUNTSYMBOLP: 80; MFFORMINGDIVP: KC; MFSOLDERINGPROP: .; TOLERANCE: D
C114 = C: FNPARTSNAMEG: CHIP CERAMIC CAPACITOR (2012); OriginalSymbolOrigin: (2540,7620); USEWITHSCHEMA: YES; FUNCN: GDM030000019; MFPACKAGEMETHOP: S; COMPONENTNAME: GDM030000019_package; GCOUNT: 1; FNCLASSCODEG: P03-03; PCODE: P03B0000004U; MFMOUNTSYMBOLP: 80; MFFORMINGDIVP: KC; MFSOLDERINGPROP: .
C115-C120 C123-C143 C145-C147 C149-C151 C153-C158 C160 C162 = C: FNPARTSNAMEG: CHIP CERAMIC CAPACITOR (1608); OriginalSymbolOrigin: (2540,7620); USEWITHSCHEMA: YES; FUNCN: GDM030000053; MFPACKAGEMETHOP: S; COMPONENTNAME: GDM030000053_package; GCOUNT: 1; FNCLASSCODEG: P03-03; MFMOUNTSYMBOLP: 80; SIZECODESMD: 1608; MFFORMINGDIVP: KC; MFSOLDERINGPROP: .; PCODE: P03B000000MS
C121 = C: as C66 on sheet 3
C122 C161 = C: FNPARTSNAMEG: CHIP CERAMIC CAPACITOR (1608); OriginalSymbolOrigin: (2540,7620); USEWITHSCHEMA: YES; FUNCN: GDM030000053; MFPACKAGEMETHOP: S; COMPONENTNAME: GDM030000053_package; GCOUNT: 1; FNCLASSCODEG: P03-03; MFMOUNTSYMBOLP: 80; MFFORMINGDIVP: KC; MFSOLDERINGPROP: .; PCODE: P03B000000MS
C144 = CP: FNPARTSCODEG: C; FNPARTSNAMEG: POSCAP (TPB); SAVEAREA0: -1450,-153,20294,13055; SAVECOUNT: 52; TIME: 15:02:55; UPDATEUSER: fukuda-y; UPDATETIME: 16:13:42; OriginalSymbolOrigin: (2540,10160); USEWITHSCHEMA: YES; FUNCN: G36030149044; GCOUNT: 1; COMPONENTNAME: G36030149044_package; FNCLASSCODEG: P03-02; PCODE: P03217004212; MFMOUNTSYMBOLP: 80; MFFORMINGDIVP: KD; MFPACKAGEMETHOP: S; MFSOLDERINGPROP: .
C148 C152 C159 C163 = CP: FNPARTSCODEG: C; FNPARTSNAMEG: POSCAP (TPB); SAVEAREA0: -1450,-153,20294,13055; SAVECOUNT: 52; TIME: 15:02:55; UPDATEUSER: fukuda-y; UPDATETIME: 16:13:42; OriginalSymbolOrigin: (2540,10160); USEWITHSCHEMA: YES; FUNCN: G36030149044; GCOUNT: 1; COMPONENTNAME: G36030149044_package; VAL1: 470uF(M); VAL2: 2V; FNCLASSCODEG: P03-02; PCODE: P03217004212; MFMOUNTSYMBOLP: 80; SIZECODESMD: 7343; MFFORMINGDIVP: KD; MFPACKAGEMETHOP: S; MFSOLDERINGPROP: .
C164 = CP: FNPARTSCODEG: C; FNPARTSNAMEG: POSCAP (TPB); SAVEAREA0: -1450,-153,20294,13055; SAVECOUNT: 52; TIME: 15:02:55; UPDATEUSER: fukuda-y; UPDATETIME: 16:13:42; OriginalSymbolOrigin: (2540,10160); USEWITHSCHEMA: YES; FUNCN: G36030149044; GCOUNT: 1; COMPONENTNAME: G36030149044_package; FNCLASSCODEG: P03-02; PCODE: P03217004212; MFMOUNTSYMBOLP: 80; SIZECODESMD: 7343; MFFORMINGDIVP: KD; MFPACKAGEMETHOP: S; MFSOLDERINGPROP: .
E7 E8 = EB1: SAVEAREA0: -19495,-9575,29572,17273; TIME: 17:33:04; UPDATEUSER: sptcae13; UPDATETIME: 17:37:19; SAVECOUNT: 4; OriginalSymbolOrigin: (0,10160)
IC9 = LT8609A: TIME: 17:49:40; UPDATEUSER: q91866sr; UPDATETIME: 14:18:47; SAVECOUNT: 44; SAVEAREA0: -19850,-898,65678,46399; OriginalSymbolOrigin: (7620,43180); USEWITHSCHEMA: YES; GCOUNT: 1; OUMEMAKER: Analog Devices; COMPONENTNAME: pinass:LT8609A_func:LT8609A
L3 L10 = L: OriginalSymbolOrigin: (2540,5080); USEWITHSCHEMA: YES; OUMEMAKER: Wurth Elektronik; COMPONENTNAME: L.L; GCOUNT: 1
R106 = R: FNPARTSNAMEG: CHIP RESISTOR (1608); OriginalSymbolOrigin: (5080,5080); FNCLASSCODEG: P01-08; PCODE: P01042049A26; USEWITHSCHEMA: YES; VAL2: 100mW; NUMBEROFELEMENT: 0; MFMOUNTSYMBOLP: 80; COMP: G36010027034; MFFORMINGDIVP: KC; MFPACKAGEMETHOP: S; MFSOLDERINGPROP: .; TOLERANCE: F; COMPONENTNAME: G36010027034_package
R107-R113 = R: FNPARTSNAMEG: CHIP RESISTOR (1608); OriginalSymbolOrigin: (5080,5080); FNCLASSCODEG: P01-08; PCODE: P01042049A26; USEWITHSCHEMA: YES; VAL2: 100mW; NUMBEROFELEMENT: 0; MFMOUNTSYMBOLP: 80; COMP: G36010027034; MFFORMINGDIVP: KC; MFPACKAGEMETHOP: S; MFSOLDERINGPROP: .; TOLERANCE: F; COMPONENTNAME: G36010027034_package; SIZECODESMD: 1608
R114 = R: FNPARTSNAMEG: CHIP RESISTOR (1608); OriginalSymbolOrigin: (5080,5080); FNCLASSCODEG: P01-08; PCODE: P01042409226; USEWITHSCHEMA: YES; NUMBEROFELEMENT: 0; MFMOUNTSYMBOLP: 80; COMP: G36010104216; MFFORMINGDIVP: KC; MFPACKAGEMETHOP: S; MFSOLDERINGPROP: .; TOLERANCE: F; COMPONENTNAME: G36010104216_package
R115 = R: FNPARTSNAMEG: CHIP RESISTOR (1608); OriginalSymbolOrigin: (5080,5080); FNCLASSCODEG: P01-08; PCODE: P01042237423; USEWITHSCHEMA: YES; NUMBEROFELEMENT: 0; MFMOUNTSYMBOLP: 80; COMP: G36010103110; MFFORMINGDIVP: KC; MFPACKAGEMETHOP: S; MFSOLDERINGPROP: .; TOLERANCE: J; COMPONENTNAME: G36010103110_package
R116 = R: FNPARTSNAMEG: CHIP RESISTOR (1608); OriginalSymbolOrigin: (5080,5080); FNCLASSCODEG: P01-08; USEWITHSCHEMA: YES; VAL2: 100mW; COMP: G36010027171; COMPONENTNAME: G36010027171_package; GCOUNT: 1; PCODE: P01042295621; NUMBEROFELEMENT: 0; MFMOUNTSYMBOLP: 80; MFFORMINGDIVP: KC; MFPACKAGEMETHOP: S; MFSOLDERINGPROP: .; TOLERANCE: F
R117 R122 = R: PARTCOMMENT: 代表セル<KC0008> がフットプリントに登録されていません。; FNPARTSNAMEG: CHIP JUMPER 1608TYPE; OriginalSymbolOrigin: (5080,5080); FNCLASSCODEG: P01-08; USEWITHSCHEMA: YES; COMP: K0100346; COMPONENTNAME: K0100346_package; GCOUNT: 1
R118 = R: FNPARTSNAMEG: CHIP RESISTOR (1608); OriginalSymbolOrigin: (5080,5080); FNCLASSCODEG: P01-08; PCODE: P01117063117; USEWITHSCHEMA: YES; VAL2: 62.5mW; NUMBEROFELEMENT: 0; MFMOUNTSYMBOLP: 80; COMP: G36010129592; MFFORMINGDIVP: KC; MFPACKAGEMETHOP: S; MFSOLDERINGPROP: .; COMPONENTNAME: G36010129592_package; GCOUNT: 1
R119 = R: FNPARTSNAMEG: CHIP RESISTOR (1608); OriginalSymbolOrigin: (5080,5080); FNCLASSCODEG: P01-08; PCODE: P01042600623; USEWITHSCHEMA: YES; VAL2: 62.5mW; NUMBEROFELEMENT: 0; MFMOUNTSYMBOLP: 80; COMP: G36010014676; MFFORMINGDIVP: KC; MFPACKAGEMETHOP: S; MFSOLDERINGPROP: .; COMPONENTNAME: G36010014676_package; GCOUNT: 1
R120 = R: FNPARTSNAMEG: CHIP RESISTOR (1608); OriginalSymbolOrigin: (5080,5080); FNCLASSCODEG: P01-08; PCODE: P01042262227; USEWITHSCHEMA: YES; VAL2: 100mW; NUMBEROFELEMENT: 0; MFMOUNTSYMBOLP: 80; COMP: G36010104254; MFFORMINGDIVP: KC; MFPACKAGEMETHOP: S; MFSOLDERINGPROP: .; COMPONENTNAME: G36010104254_package; GCOUNT: 1; TOLERANCE: F
R121 = R: FNPARTSNAMEG: CHIP RESISTOR (1608); OriginalSymbolOrigin: (5080,5080); FNCLASSCODEG: P01-08; USEWITHSCHEMA: YES; VAL2: 100mW; COMP: G36010027034; COMPONENTNAME: G36010027034_package; GCOUNT: 1; PCODE: P01042049A26; NUMBEROFELEMENT: 0; MFMOUNTSYMBOLP: 80; MFFORMINGDIVP: KC; MFPACKAGEMETHOP: S; MFSOLDERINGPROP: .; TOLERANCE: F
R123 R124 = R: FNPARTSNAMEG: CHIP RESISTOR (1608); OriginalSymbolOrigin: (5080,5080); FNCLASSCODEG: P01-08; PCODE: P01042521225; USEWITHSCHEMA: YES; VAL2: 100mW; NUMBEROFELEMENT: 0; MFMOUNTSYMBOLP: 80; COMP: G36010027324; MFFORMINGDIVP: KC; MFPACKAGEMETHOP: S; MFSOLDERINGPROP: .; TOLERANCE: F; COMPONENTNAME: G36010027324_package; GCOUNT: 1; SIZECODESMD: 1608
S1 = SWMX8: OriginalSymbolOrigin: (5080,30480); USEWITHSCHEMA: YES; OUMEMAKER: CTS; COMPONENTNAME: SWMX8.SWMX8; GCOUNT: 1
U?#4 = WAKU_DEF100: PLOTTIME: HH:MM; SAVEAREA0: 330961,54,387907,31546; TIME: 19:23:07; UPDATEUSER: sptcae13; UPDATETIME: 17:47:42; SAVECOUNT: 8; OriginalSymbolOrigin: (10160,284480)

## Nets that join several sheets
LGND: 1 (46 pins), 2 (29 pins), 3 (75 pins), 4 (76 pins)
ISEN1: 2 (C48.1 IC2.32), 3 (R76.2)
ISEN2: 2 (C50.1 IC2.26), 3 (R77.2)
ISEN3: 2 (C52.1 IC2.35), 3 (R78.2)
ISEN4: 2 (C54.1 IC2.29), 3 (R79.2)
ISEN5: 2 (C56.1 IC2.23), 3 (R80.2)
SIGN6707: 2 (IC2.31), 3 (C61.1 IC3.4)
SIGN6708: 2 (IC2.25), 3 (C62.1 IC4.4)
SIGN6709: 2 (IC2.36), 3 (C60.1 IC5.4)
SIGN6710: 2 (IC2.30), 3 (C84.1 IC6.4)
SIGN6711: 2 (IC2.24), 3 (C85.1 IC7.4)
SIGN7002: 2 (16 pins), 3 (5 pins), 4 (54 pins)
SIGN7186: 2 (R55.1), 4 (R113.1 S1.16)
SIGN7187: 2 (R54.1), 4 (R112.1 S1.15)
SIGN7204: 2 (C40.1 IC2.40 R67.2), 4 (IC9.8 R121.1)
VCC5: 2 (13 pins), 3 (20 pins), 4 (15 pins)
VID2: 2 (R53.1), 4 (R111.1 S1.14)
VID3: 2 (R52.1), 4 (R110.1 S1.13)
VID4: 2 (R63.1), 4 (R109.1 S1.12)
VID5: 2 (R62.1), 4 (R108.1 S1.11)
VID6: 2 (R61.1), 4 (R107.1 S1.10)
VID7: 2 (R60.1), 4 (R106.1 S1.9)
VP_12V: 1 (16 pins), 3 (40 pins), 4 (L3.1)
